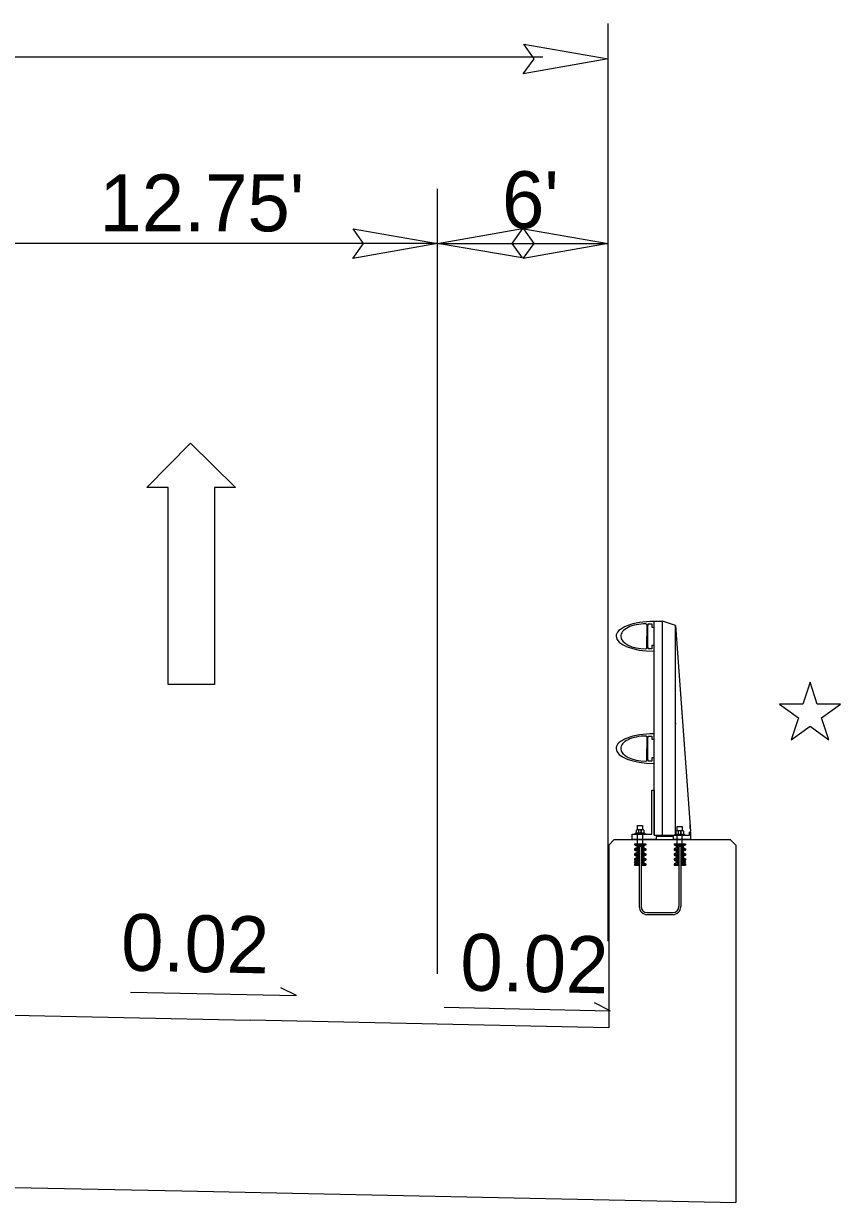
# Model space of a CAD drawing. Extents: x 573813 to 575363, y -54752 to -53123.
# Drawn here: x 574392.14 to 574420.88, y -54173.5 to -54132.03 of the extents above; entities that cross this region are included whole.
import ezdxf

# ---------------------------------------------------------------- set-up
doc = ezdxf.new("R2010")
doc.units = 0
for name, color, linetype in [('Old_Level_1', 7, 'Continuous'), ('Old_Level_11', 7, 'Continuous'), ('Old_Level_4', 7, 'Continuous'), ('Prop RDY Traffic Signal CELL', 7, 'Continuous'), ('Typical Bridge Rail Two Bar CELL', 7, 'Continuous')]:
    doc.layers.add(name, color=color, linetype=linetype)

msp = doc.modelspace()

# ---------------------------------------------------------------- linework, layer by layer
at = {"layer": 'Old_Level_1'}
for p, q in [((574395.906, -54166.103), (574401.745, -54166.225)), ((574401.745, -54166.225), (574401.194, -54165.95)), ((574412.774, -54166.754), (574412.224, -54166.48)), ((574390.107, -54166.881), (574400.108, -54167.089)), ((574406.936, -54166.633), (574412.774, -54166.754)), ((574412.725, -54167.352), (574400.108, -54167.089)), ((574377.946, -54172.681), (574397.712, -54173.092)), ((574397.712, -54173.095), (574417.198, -54173.499))]:
    msp.add_line(p, q, dxfattribs=at)
at = {"layer": 'Old_Level_11'}
for p, q in [((574412.707, -54164.309), (574412.708, -54132.025)), ((574410.403, -54133.212), (574345.602, -54133.212)), ((574406.707, -54165.46), (574406.707, -54137.845)), ((574406.707, -54139.761), (574389.07, -54139.761)), ((574406.707, -54139.761), (574412.707, -54139.761))]:
    msp.add_line(p, q, dxfattribs=at)
for points in [[(574409.738, -54132.751), (574412.707, -54133.262), (574409.721, -54133.79), (574410.1, -54133.262)], [(574403.737, -54139.249), (574406.707, -54139.761), (574403.721, -54140.289), (574404.1, -54139.761)], [(574409.677, -54140.272), (574406.707, -54139.761), (574409.694, -54139.233), (574409.315, -54139.761)], [(574409.737, -54139.249), (574412.707, -54139.761), (574409.721, -54140.288), (574410.1, -54139.761)]]:
    msp.add_lwpolyline(points, close=True, dxfattribs=at)
at = {"layer": 'Old_Level_4'}
for p, q in [((574396.483, -54148.347), (574398.018, -54146.788)), ((574398.018, -54146.788), (574399.602, -54148.347)), ((574397.226, -54148.347), (574396.483, -54148.347)), ((574397.226, -54155.278), (574397.226, -54148.347)), ((574399.602, -54148.347), (574398.859, -54148.347)), ((574398.859, -54148.347), (574398.859, -54155.278)), ((574398.859, -54155.278), (574397.226, -54155.278))]:
    msp.add_line(p, q, dxfattribs=at)
at = {"layer": 'Prop RDY Traffic Signal CELL'}
msp.add_lwpolyline([(574419.554, -54155.97), (574418.738, -54155.97), (574419.398, -54156.45), (574419.146, -54157.228), (574419.807, -54156.747), (574420.469, -54157.227), (574420.216, -54156.45), (574420.877, -54155.97), (574420.06, -54155.97), (574419.807, -54155.192), (574419.554, -54155.97)], dxfattribs=at)
at = {"layer": 'Typical Bridge Rail Two Bar CELL'}
for p, q in [((574414.068, -54153.174), (574414.068, -54153.583)), ((574414.32, -54153.049), (574414.621, -54153.049)), ((574414.32, -54160.583), (574414.32, -54153.049)), ((574415.077, -54153.198), (574414.621, -54153.049)), ((574414.621, -54160.583), (574414.621, -54153.049)), ((574415.077, -54160.583), (574415.077, -54153.198)), ((574415.077, -54153.198), (574415.603, -54160.433)), ((574414.068, -54153.993), (574414.068, -54153.583)), ((574415.077, -54156.655), (574415.094, -54156.655)), ((574414.068, -54157.123), (574414.068, -54157.532)), ((574414.068, -54157.941), (574414.068, -54157.532)), ((574413.742, -54160.381), (574413.742, -54160.239)), ((574413.742, -54160.239), (574413.914, -54160.239)), ((574413.914, -54160.239), (574413.914, -54160.381)), ((574415.138, -54160.42), (574415.138, -54160.279)), ((574415.138, -54160.279), (574415.309, -54160.279)), ((574415.309, -54160.279), (574415.309, -54160.42)), ((574415.589, -54160.349), (574415.589, -54160.216)), ((574413.734, -54160.879), (574413.734, -54160.545)), ((574413.923, -54160.879), (574413.923, -54160.545)), ((574415.139, -54160.917), (574415.139, -54160.583)), ((574415.313, -54160.917), (574415.313, -54160.583)), ((574415.603, -54160.583), (574415.603, -54160.433)), ((574412.92, -54160.734), (574412.725, -54160.929)), ((574412.725, -54160.929), (574412.725, -54167.352)), ((574412.92, -54160.734), (574417.002, -54160.734)), ((574413.635, -54160.879), (574414.035, -54160.879)), ((574413.635, -54160.923), (574414.035, -54160.923)), ((574413.635, -54161.057), (574413.801, -54161.057)), ((574413.635, -54161.101), (574413.801, -54161.101)), ((574413.723, -54160.968), (574413.801, -54160.968)), ((574413.723, -54161.013), (574413.801, -54161.013)), ((574413.801, -54160.967), (574413.801, -54163.09)), ((574413.801, -54160.968), (574413.868, -54160.968)), ((574413.868, -54160.967), (574413.868, -54163.09)), ((574413.868, -54160.968), (574413.946, -54160.968)), ((574413.868, -54161.013), (574413.946, -54161.013)), ((574413.868, -54161.057), (574414.035, -54161.057)), ((574413.868, -54161.101), (574414.035, -54161.101)), ((574415.028, -54160.879), (574415.429, -54160.879)), ((574415.028, -54160.923), (574415.429, -54160.923)), ((574415.028, -54161.057), (574415.196, -54161.057)), ((574415.028, -54161.101), (574415.196, -54161.101)), ((574415.118, -54160.968), (574415.196, -54160.968)), ((574415.118, -54161.013), (574415.196, -54161.013)), ((574415.196, -54160.967), (574415.262, -54160.967)), ((574415.196, -54160.967), (574415.196, -54163.09)), ((574415.262, -54160.967), (574415.262, -54163.09)), ((574415.262, -54160.968), (574415.341, -54160.968)), ((574415.262, -54161.013), (574415.341, -54161.013)), ((574415.262, -54161.057), (574415.429, -54161.057)), ((574415.262, -54161.101), (574415.429, -54161.101)), ((574417.198, -54160.929), (574417.002, -54160.734)), ((574417.198, -54160.929), (574417.198, -54173.499)), ((574413.635, -54161.234), (574413.801, -54161.234)), ((574413.635, -54161.28), (574413.801, -54161.28)), ((574413.635, -54161.412), (574413.801, -54161.412)), ((574413.635, -54161.456), (574413.801, -54161.456)), ((574413.723, -54161.146), (574413.801, -54161.146)), ((574413.723, -54161.19), (574413.801, -54161.19)), ((574413.723, -54161.324), (574413.801, -54161.324)), ((574413.723, -54161.368), (574413.801, -54161.368)), ((574413.723, -54161.501), (574413.801, -54161.501)), ((574413.723, -54161.545), (574413.801, -54161.545)), ((574413.868, -54161.146), (574413.946, -54161.146)), ((574413.868, -54161.19), (574413.946, -54161.19)), ((574413.868, -54161.234), (574414.035, -54161.234)), ((574413.868, -54161.28), (574414.035, -54161.28)), ((574413.868, -54161.324), (574413.946, -54161.324)), ((574413.868, -54161.368), (574413.946, -54161.368)), ((574413.868, -54161.412), (574414.035, -54161.412)), ((574413.868, -54161.456), (574414.035, -54161.456)), ((574413.868, -54161.501), (574413.946, -54161.501)), ((574413.868, -54161.545), (574413.946, -54161.545)), ((574415.028, -54161.234), (574415.196, -54161.234)), ((574415.028, -54161.28), (574415.196, -54161.28)), ((574415.028, -54161.412), (574415.196, -54161.412)), ((574415.028, -54161.456), (574415.196, -54161.456)), ((574415.118, -54161.146), (574415.196, -54161.146)), ((574415.118, -54161.19), (574415.196, -54161.19)), ((574415.118, -54161.324), (574415.196, -54161.324)), ((574415.118, -54161.368), (574415.196, -54161.368)), ((574415.118, -54161.501), (574415.196, -54161.501)), ((574415.118, -54161.545), (574415.196, -54161.545)), ((574415.262, -54161.146), (574415.341, -54161.146)), ((574415.262, -54161.19), (574415.341, -54161.19)), ((574415.262, -54161.234), (574415.429, -54161.234)), ((574415.262, -54161.28), (574415.429, -54161.28)), ((574415.262, -54161.324), (574415.341, -54161.324)), ((574415.262, -54161.368), (574415.341, -54161.368)), ((574415.262, -54161.412), (574415.429, -54161.412)), ((574415.262, -54161.456), (574415.429, -54161.456)), ((574415.262, -54161.501), (574415.341, -54161.501)), ((574415.262, -54161.545), (574415.341, -54161.545)), ((574413.635, -54161.59), (574413.801, -54161.59)), ((574413.635, -54161.634), (574413.801, -54161.634)), ((574413.868, -54161.59), (574414.035, -54161.59)), ((574413.868, -54161.634), (574414.035, -54161.634)), ((574415.028, -54161.59), (574415.196, -54161.59)), ((574415.028, -54161.634), (574415.196, -54161.634)), ((574415.262, -54161.59), (574415.429, -54161.59)), ((574415.262, -54161.634), (574415.429, -54161.634)), ((574414.081, -54163.303), (574414.981, -54163.303)), ((574414.081, -54163.37), (574414.981, -54163.37))]:
    msp.add_line(p, q, dxfattribs=at)
for points in [[(574414.32, -54154.105), (574414.32, -54153.91), (574414.239, -54153.91), (574414.239, -54153.942), (574414.247, -54153.942), (574414.247, -54154.024), (574414.117, -54154.024), (574414.101, -54153.898), (574414.101, -54153.583), (574414.101, -54153.268), (574414.117, -54153.142), (574414.247, -54153.142), (574414.247, -54153.224), (574414.239, -54153.224), (574414.239, -54153.257), (574414.32, -54153.257), (574414.32, -54153.06)], [(574414.32, -54158.054), (574414.32, -54157.858), (574414.239, -54157.858), (574414.239, -54157.891), (574414.247, -54157.891), (574414.247, -54157.973), (574414.117, -54157.973), (574414.101, -54157.847), (574414.101, -54157.532), (574414.101, -54157.217), (574414.117, -54157.092), (574414.247, -54157.092), (574414.247, -54157.173), (574414.239, -54157.173), (574414.239, -54157.205), (574414.32, -54157.205), (574414.32, -54157.01)], [(574413.548, -54160.734), (574413.548, -54160.545), (574414.244, -54160.545), (574414.244, -54158.999), (574414.32, -54158.999), (574414.32, -54160.583), (574415.567, -54160.583), (574415.567, -54160.472), (574415.603, -54160.472), (574415.603, -54160.734), (574415.002, -54160.734), (574415.002, -54160.63), (574414.396, -54160.63), (574414.396, -54160.734), (574413.548, -54160.734)], [(574413.654, -54160.546), (574413.654, -54160.512), (574413.826, -54160.512), (574413.999, -54160.512), (574413.999, -54160.546)], [(574413.702, -54160.514), (574413.702, -54160.404), (574413.722, -54160.383), (574413.935, -54160.383), (574413.956, -54160.404), (574413.956, -54160.514), (574413.702, -54160.514), (574413.787, -54160.514), (574413.787, -54160.404), (574413.765, -54160.383), (574413.787, -54160.404), (574413.807, -54160.383), (574413.851, -54160.383), (574413.872, -54160.404), (574413.872, -54160.514), (574413.872, -54160.404), (574413.892, -54160.383)], [(574415.053, -54160.585), (574415.053, -54160.551), (574415.225, -54160.551), (574415.396, -54160.551), (574415.396, -54160.585)], [(574415.097, -54160.551), (574415.097, -54160.442), (574415.119, -54160.42), (574415.329, -54160.42), (574415.352, -54160.442), (574415.352, -54160.551), (574415.097, -54160.551), (574415.182, -54160.551), (574415.182, -54160.442), (574415.16, -54160.42), (574415.182, -54160.442), (574415.202, -54160.42), (574415.246, -54160.42), (574415.267, -54160.442), (574415.267, -54160.551), (574415.267, -54160.442), (574415.289, -54160.42)], [(574413.633, -54160.879), (574413.633, -54160.923), (574413.723, -54160.968), (574413.723, -54161.013), (574413.633, -54161.057), (574413.633, -54161.101), (574413.723, -54161.146), (574413.723, -54161.19), (574413.633, -54161.234), (574413.633, -54161.28), (574413.723, -54161.324), (574413.723, -54161.368), (574413.633, -54161.412), (574413.633, -54161.456), (574413.723, -54161.501), (574413.723, -54161.545), (574413.633, -54161.59), (574413.633, -54161.634)], [(574414.035, -54160.879), (574414.035, -54160.923), (574413.946, -54160.968), (574413.946, -54161.013), (574414.035, -54161.057), (574414.035, -54161.101), (574413.946, -54161.146), (574413.946, -54161.19), (574414.035, -54161.234), (574414.035, -54161.28), (574413.946, -54161.324), (574413.946, -54161.368), (574414.035, -54161.412), (574414.035, -54161.456), (574413.946, -54161.501), (574413.946, -54161.545), (574414.035, -54161.59), (574414.035, -54161.634)], [(574415.028, -54160.879), (574415.028, -54160.923), (574415.116, -54160.968), (574415.116, -54161.013), (574415.028, -54161.057), (574415.028, -54161.101), (574415.116, -54161.146), (574415.116, -54161.19), (574415.028, -54161.234), (574415.028, -54161.28), (574415.116, -54161.324), (574415.116, -54161.368), (574415.028, -54161.412), (574415.028, -54161.456), (574415.116, -54161.501), (574415.116, -54161.545), (574415.028, -54161.59), (574415.028, -54161.634)], [(574415.429, -54160.879), (574415.429, -54160.923), (574415.341, -54160.968), (574415.341, -54161.013), (574415.429, -54161.057), (574415.429, -54161.101), (574415.341, -54161.146), (574415.341, -54161.19), (574415.429, -54161.234), (574415.429, -54161.28), (574415.341, -54161.324), (574415.341, -54161.368), (574415.429, -54161.412), (574415.429, -54161.456), (574415.341, -54161.501), (574415.341, -54161.545), (574415.429, -54161.59), (574415.429, -54161.634)]]:
    msp.add_lwpolyline(points, dxfattribs=at)
for centre in [(574413.669, -54161.523), (574415.394, -54161.523)]:
    msp.add_circle(centre, 0.0334, dxfattribs=at)
for centre, radius, start, end in [((574414.036, -54153.174), 0.0313, 0, 90), ((574414.036, -54153.992), 0.0313, 270, 0), ((574414.036, -54157.123), 0.0313, 0, 90), ((574414.036, -54157.941), 0.0313, 270, 0), ((574414.081, -54163.09), 0.28, 180, 270), ((574414.081, -54163.09), 0.214, 180, 270), ((574414.981, -54163.09), 0.214, 270, 0), ((574414.981, -54163.09), 0.28, 270, 0)]:
    msp.add_arc(centre, radius, start, end, dxfattribs=at)
for centre, major_axis, ratio, start_param, end_param in [((574414.321, -54153.583), (-1.338, 0), 0.39036, 4.712404, 6.283584), ((574414.036, -54153.583), (-0.889, 0), 0.495501, 4.712489, 6.283652), ((574414.321, -54153.583), (-1.338, 0), 0.39036, 0.000398, 1.570782), ((574414.036, -54153.583), (-0.889, 0), 0.495501, 0.000467, 1.570696), ((574414.321, -54157.532), (-1.338, 0), 0.39036, 4.712404, 6.283584), ((574414.036, -54157.532), (-0.889, 0), 0.495501, 4.712489, 6.283652), ((574414.321, -54157.532), (-1.338, 0), 0.39036, 0.000398, 1.570782), ((574414.036, -54157.532), (-0.889, 0), 0.495501, 0.000467, 1.570696)]:
    msp.add_ellipse(centre, major_axis=major_axis, ratio=ratio, start_param=start_param, end_param=end_param, dxfattribs=at)

# ---------------------------------------------------------------- texts
at = {"layer": 'Old_Level_1'}
for p in [(574395.556, -54165.337), (574407.49, -54166.038)]:
    msp.add_text('0.02', height=2, rotation=358.8082, dxfattribs=at).set_placement(p)
at = {"layer": 'Old_Level_11'}
for s, p in [("12.75'", (574394.814, -54139.334)), ("6'", (574408.973, -54139.222))]:
    msp.add_text(s, height=2, rotation=359.9999, dxfattribs=at).set_placement(p)

doc.saveas('drawing.dxf')
